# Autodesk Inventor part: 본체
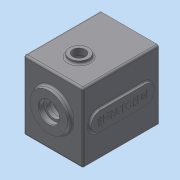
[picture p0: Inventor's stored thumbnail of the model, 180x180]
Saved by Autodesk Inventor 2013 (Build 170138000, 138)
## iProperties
Created: 2016-02
Part Number: 본체
Material: 알루미늄 6061
Document SubType Name: Modeling
Designer: mduedu
Density: 2.71 g/cm^3
Author: mduedu
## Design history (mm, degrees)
sketch "스케치1"
  geometry: L1 (-47, -47)-(47, -47); L2 (47, -47)-(47, 63); L3 (47, 63)-(-47, 63); L4 (-47, 63)-(-47, -47); 2 further points
  constraints: 8 end point, 2 parallel, 1 horizontal, 1 midpoint, 1 perpendicular, 1 vertical alignment
  dimensions: "d0" = 94 distance of L2.end L3.end; "d155" = 110 distance of L1.end L2.end; "d156" = 47 distance from line of L1 point (0, 0)
extrude "돌출1" new body sketch "스케치1" distance "d2" = 120; taper "d3" = 0 deg
sketch "스케치3"
  geometry: L1 (47, -47)-(-47, -47) reference; L2 (47, 63)-(47, -47) reference; L3 (-47, 63)-(47, 63) reference; L4 (-47, -47)-(-47, 63) reference; L5 (37, 53)-(37, -37); L6 (37, -37)-(-37, -37); L7 (-37, -37)-(-37, 53); L8 (-37, 53)-(37, 53); 1 further point
  constraints: 8 end point, 3 other
  dimensions: "d226" = 10 distance between parallel lines of L8 L3
extrude "돌출3" cut sketch "스케치3" distance "d11" = 110; taper "d12" = 0 deg
sketch "스케치4"
  geometry: C1 r 21 at (0, 11); 1 further point
  constraints: 1 centre point, 1 vertical alignment
  dimensions: "d13" = 21 radius of C1; "d227" = 11 distance of point (0, 0) C1.centre
extrude "돌출4" join sketch "스케치4" distance "d16" = 7; taper "d17" = 0 deg
sketch "스케치5"
  geometry: C1 r 15 at (0, -20); 1 further point
  constraints: 1 centre point, 1 vertical alignment
  dimensions: "d18" = 15 radius of C1; "d20" = 20 distance of point (0, 0) C1.centre
extrude "돌출5" join sketch "스케치5" distance "d21" = 7; taper "d22" = 0 deg
sketch "스케치6"
  geometry: C1 r 30 at (0, 11); A1 r 21 centre (0, 11) between (8.978, -7.984) and (-8.978, -7.984) reference; 1 further point
  constraints: 1 centre point, 1 coincident
  dimensions: "d228" = 60 diameter of C1
extrude "돌출6" join sketch "스케치6" distance "d25" = 7; taper "d26" = -3 deg
hole "구멍1" diameter "d29" = 35; stored, may be unused: countersink angle "d33" = 90 deg, drill point angle "d35" = 0 deg; dims "d27" = 10, "d28" = 10, "d30" = 6, "d31" = 4, "d32" = 2, "d34" = 10
hole "구멍2" diameter "d38" = 22; stored, may be unused: countersink angle "d42" = 90 deg, drill point angle "d44" = 0 deg; dims "d36" = 10, "d37" = 10, "d39" = 6, "d40" = 4, "d41" = 2, "d43" = 7
hole "구멍3" diameter "d47" = 19; stored, may be unused: countersink angle "d51" = 90 deg, drill point angle "d53" = 0 deg; dims "d45" = 10, "d46" = 10, "d48" = 6, "d49" = 4, "d50" = 2, "d52" = 1
hole "구멍4" diameter "d56" = 32; stored, may be unused: countersink angle "d60" = 90 deg, drill point angle "d62" = 0 deg; dims "d57" = 6, "d58" = 4, "d59" = 2, "d61" = 8, "d220" = 10, "d221" = 10
hole "구멍5" diameter "d65" = 25; stored, may be unused: countersink angle "d69" = 90 deg, drill point angle "d71" = 0 deg; dims "d63" = 10, "d64" = 10, "d66" = 6, "d67" = 4, "d68" = 2, "d70" = 8
fillet "모깎기2" dims "d73" = 0.3
fillet "모깎기3" dims "d74" = 2
chamfer "모따기1" distance "d75" = 1; stored, may be unused: second distance "d76" = 2, angle "d77" = 45 deg
fillet "모깎기4" dims "d78" = 3
fillet "모깎기23" dims "d240" = 1
fillet "모깎기20" dims "d229" = 3
sketch "스케치23"
  geometry: L1 (-37, 53)-(37, 53) reference; L2 (37, 53)-(37, -37) reference; L3 (37, -37)-(-37, -37) reference; L4 (-37, -37)-(-37, 53) reference; L5 (44, -47)-(-44, -47) reference; L6 (47, 60)-(47, -44) reference; L7 (-44, 63)-(44, 63) reference; L8 (-47, -44)-(-47, 60) reference; C1 r 10 at (-37, 53); C2 r 10 at (37, 53); C3 r 10 at (-37, -37); C4 r 10 at (37, -37); A1 r 3 centre (-44, -44) between (-47, -44) and (-44, -47) reference; A2 r 3 centre (44, -44) between (44, -47) and (47, -44) reference; A3 r 3 centre (44, 60) between (47, 60) and (44, 63) reference; A4 r 3 centre (-44, 60) between (-44, 63) and (-47, 60) reference; 1 further point
  constraints: 4 centre point, 4 coincident, 3 equal radius
  dimensions: "d230" = 20 diameter of C1
extrude "돌출22" join sketch "스케치23" stored distance "d235" = 10; taper "d236" = 0 deg
fillet "모깎기21" dims "d237" = 3
node "작업 평면1"
fillet "모깎기22" dims "d239" = 1
sketch "스케치12"
  geometry: A1 r 10 centre (-37, 53) between (-34.692, 43.27) and (-27.27, 50.692) reference; A2 r 10 centre (37, 53) between (27.27, 50.692) and (34.692, 43.27) reference; A3 r 10 centre (37, -37) between (34.692, -27.27) and (27.27, -34.692) reference; A4 r 10 centre (-37, -37) between (-27.27, -34.692) and (-34.692, -27.27) reference; 5 further points
  constraints: 4 coincident
hole "구멍6" sketch "스케치12" at (-37, 53), (37, 53), (37, -37), (-37, -37) diameter "d122" = 3.242; stored, may be unused: countersink angle "d126" = 90 deg, drill point angle "d128" = 120 deg; dims "d123" = 7, "d124" = 4, "d125" = 2, "d127" = 9
sketch "스케치20"
  geometry: L1 (44, 0)-(-44, 0) reference; L2 (44, -120)-(-44, -120) reference; L3 (0, 0)-(0, -120); L4 (-44, -120)-(-44, 0) reference; L5 (44, 0)-(44, -120) reference; C1 r 10 at (0, -79)
  constraints: 2 end point, 1 centre point, 1 midpoint, 1 point on line
  dimensions: "d189" = 20 diameter of C1; "d190" = 41 distance from line of C1.centre L2
extrude "돌출19" cut sketch "스케치20" stored distance "d191" = 10; taper "d192" = 0 deg
sketch "스케치18"
  geometry: C1 r 15 at (0, -79); C2 r 10 at (0, -79) reference; 1 further point
  constraints: 1 centre point, 1 concentric
  dimensions: "d174" = 30 diameter of C1
extrude "돌출17" join sketch "스케치18" distance "d175" = 5; taper "d176" = 0 deg
fillet "모깎기16" dims "d177" = 3
sketch "스케치19"
  geometry: C1 r 15 at (24.351, 79); C2 r 10 at (24.351, 79) reference; 1 further point
  constraints: 1 centre point, 1 concentric
  dimensions: "d178" = 30 diameter of C1
extrude "돌출18" cut sketch "스케치19" distance "d181" = 5; taper "d182" = 0 deg
chamfer "모따기5" distance "d183" = 1; stored, may be unused: second distance "d184" = 2, angle "d185" = 45 deg
fillet "모깎기24" dims "d242" = 3, "d243" = 3
sketch "스케치24"
  geometry: L1 (-95, 67)-(-25, 67); L2 (-25, 67)-(-25, 37); L3 (-25, 37)-(-95, 37); L4 (-95, 37)-(-95, 67); L5 (0, 0)-(0, 104) reference; L6 (-95, 52)-(-25, 52); L7 (-60, 67)-(-60, 37); A1 r 15 centre (-95, 52) between (-95, 37) and (-95, 67); A2 r 15 centre (-25, 52) between (-25, 67) and (-25, 37); A3 r 15 centre (-25, 52) between (-25, 37) and (-25, 67); A4 r 15 centre (-95, 52) between (-95, 67) and (-95, 37); 2 further points
  constraints: 12 end point, 8 point on circle, 5 midpoint, 4 centre point, 2 parallel, 2 perpendicular, 1 horizontal, 1 horizontal alignment
  dimensions: "d244" = 60 distance between parallel lines of L7 L5; "d245" = 100 dimension on A2 A1; "d246" = 30 distance between parallel lines of L3 L1
extrude "돌출23" join sketch "스케치24" distance "d247" = 3; taper "d248" = 0 deg
fillet "모깎기25" dims "d249" = 3
sketch "스케치25"
  geometry: L1 (-25, 67)-(-95, 67) reference; L2 (-95, 37)-(-25, 37) reference; A1 r 15 centre (-95, 52) between (-95, 67) and (-95, 37) reference; A2 r 15 centre (-25, 52) between (-25, 37) and (-25, 67) reference; 3 further points
  constraints: 1 horizontal alignment, 1 midpoint, 1 vertical alignment, 1 other
feature "엠보싱3" sketch "스케치25" dims "d250" = 0.5, "d251" = 0
sketch "스케치26"
  geometry: L1 (14.367, 127)-(73.633, 127) reference; L2 (0, 0)-(88, 0) reference; L3 (88, 120)-(0, 120) reference; 5 further points
  constraints: 3 vertical alignment, 2 midpoint
  dimensions: "d252" = 35 distance from line of point (44, 35) L2; "d253" = 35 distance from line of point (44, 85) L3; "d254" = 50 distance of point (44, 35) point (44, 85) (derived)
hole "구멍8" sketch "스케치26" at (44, 85), (44, 35) diameter "d255" = 6.647; stored, may be unused: countersink angle "d259" = 90 deg, drill point angle "d261" = 118 deg; dims "d256" = 6, "d257" = 4, "d258" = 2, "d260" = 8
node "솔리드1"
node "투영된 루프1"
node "투영된 루프4"
node "투영된 루프5"
node "투영된 루프6"
